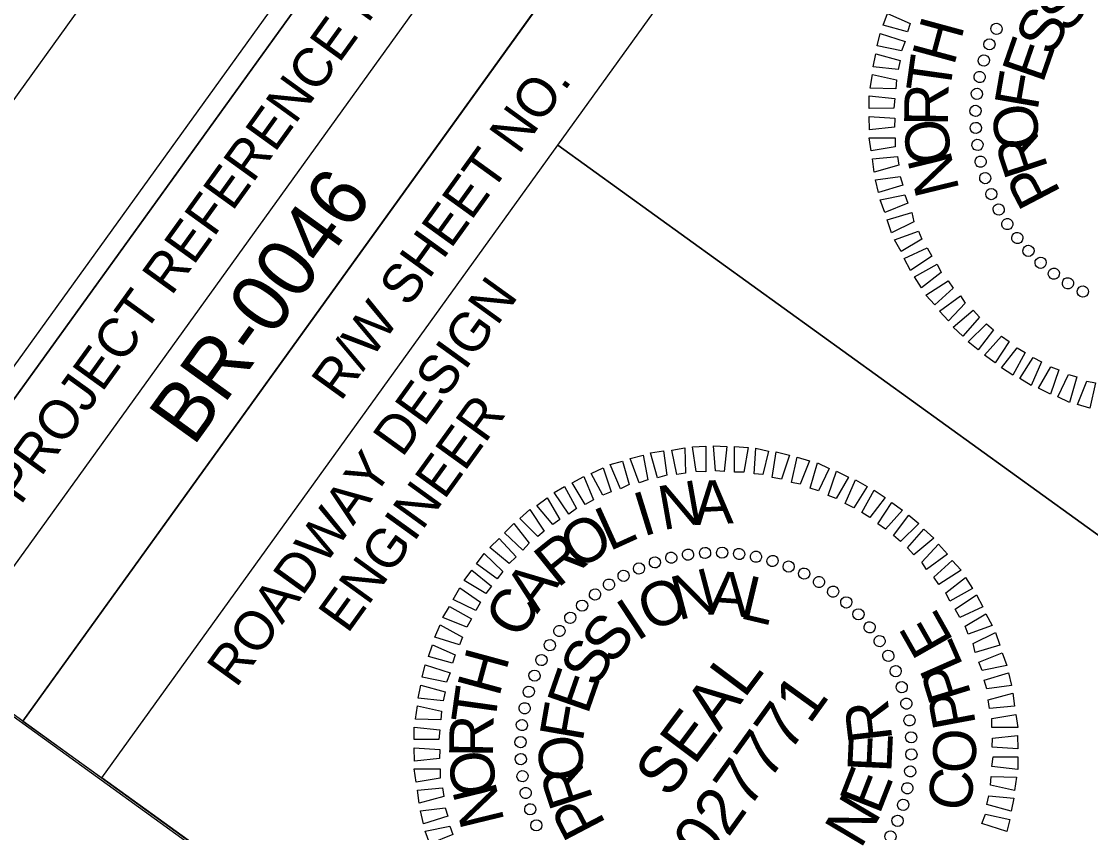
# Model space of a CAD drawing. Extents: x 2189185 to 2191058, y 386509 to 388561.
# Drawn here: x 2190081.4 to 2190218.6, y 388297.3 to 388401.3 of the extents above; entities that cross this region are included whole.
import ezdxf

# ---------------------------------------------------------------- set-up
doc = ezdxf.new("R2010")
doc.units = 0
for name, color, linetype in [('Sheet Clip Boundary CELL', 7, 'Continuous'), ('Sheet Cutting Line CELL', 7, 'Continuous'), ('Sheet Data Field CELL', 7, 'Continuous'), ('Sheet Plan CELL', 7, 'Continuous'), ('Sheet Plan Layout CELL', 7, 'Continuous'), ('Sheet Plot Border Inside CELL', 7, 'Continuous'), ('Sheet Plot Border Outside CELL', 7, 'Continuous'), ('Sheet Professional Seal CELL', 7, 'Continuous'), ('Sheet Sticker Exception Certification CELL', 7, 'Continuous')]:
    doc.layers.add(name, color=color, linetype=linetype)

msp = doc.modelspace()

# ---------------------------------------------------------------- linework, layer by layer
at = {"layer": 'Sheet Clip Boundary CELL'}
msp.add_lwpolyline([(2190166.8, 386710.01), (2190905.33, 387738.93), (2190256.9, 388232.77), (2190233.39, 388201.76), (2190061.07, 388326.03), (2189853.58, 388001.31), (2189912.61, 387915.43), (2189757.61, 387710.51), (2189654.64, 387750.49), (2189330.08, 387312.42)], close=True, dxfattribs=at)
at = {"layer": 'Sheet Cutting Line CELL'}
msp.add_line((2190169.94, 388515.44), (2189185.21, 387149.98), dxfattribs=at)
at = {"layer": 'Sheet Plan CELL'}
for p, q in [((2190071.39, 388318.9), (2190188.41, 388481.15)), ((2190081.56, 388311.57), (2190198.55, 388473.83)), ((2190081.56, 388311.57), (2190198.55, 388473.83)), ((2190150.21, 388385.42), (2190241.44, 388319.64)), ((2190081.56, 388311.57), (2190091.69, 388304.27))]:
    msp.add_line(p, q, dxfattribs=at)
for points in [[(2190178.25, 388488.52), (2189300.83, 387271.86), (2190152.47, 386657.68), (2191029.88, 387874.32)], [(2190061.21, 388326.25), (2190178.25, 388488.52), (2190198.55, 388473.83), (2190081.56, 388311.57)], [(2190150.21, 388385.42), (2190208.69, 388466.52), (2190299.95, 388400.72), (2190241.47, 388319.6)], [(2190152.47, 386657.68), (2189300.84, 387271.83), (2190061.21, 388326.25), (2190182.93, 388238.48), (2190299.95, 388400.72), (2191029.88, 387874.32)], [(2190091.69, 388304.27), (2190150.21, 388385.42), (2190241.47, 388319.6), (2190182.93, 388238.48)]]:
    msp.add_lwpolyline(points, close=True, dxfattribs=at)
at = {"layer": 'Sheet Plan Layout CELL'}
msp.add_lwpolyline([(2190209.82, 388170.73), (2190349.78, 388364.8), (2190178.26, 388488.53), (2190038.29, 388294.44)], close=True, dxfattribs=at)
at = {"layer": 'Sheet Plot Border Inside CELL'}
msp.add_lwpolyline([(2190064.73, 386531.72), (2191039.21, 387882.98), (2190183.53, 388500.09), (2189209.04, 387148.83)], close=True, dxfattribs=at)
at = {"layer": 'Sheet Plot Border Outside CELL'}
msp.add_lwpolyline([(2190073.35, 386509.48), (2191058.08, 387874.94), (2190169.94, 388515.44), (2189185.21, 387149.98)], close=True, dxfattribs=at)
at = {"layer": 'Sheet Professional Seal CELL'}
for p, q in [((2190206.5, 388400.33), (2190206.5, 388400.33)), ((2190205.54, 388398.31), (2190205.54, 388398.31)), ((2190204.8, 388396.26), (2190204.8, 388396.26)), ((2190204.28, 388394.17), (2190204.28, 388394.17)), ((2190203.95, 388392), (2190203.95, 388392)), ((2190203.77, 388389.79), (2190203.77, 388389.79)), ((2190203.76, 388387.63), (2190203.76, 388387.63)), ((2190204.01, 388385.42), (2190204.01, 388385.42)), ((2190204.39, 388383.3), (2190204.39, 388383.3)), ((2190205.02, 388381.18), (2190205.02, 388381.18)), ((2190205.75, 388379.11), (2190205.75, 388379.11)), ((2190206.75, 388377.16), (2190206.75, 388377.16)), ((2190207.84, 388375.26), (2190207.84, 388375.26)), ((2190209.14, 388373.46), (2190209.14, 388373.46)), ((2190210.58, 388371.87), (2190210.58, 388371.87)), ((2190212.12, 388370.33), (2190212.12, 388370.33)), ((2190213.81, 388368.92), (2190213.81, 388368.92)), ((2190215.63, 388367.67), (2190215.63, 388367.67)), ((2190217.55, 388366.66), (2190217.55, 388366.66)), ((2190169.11, 388333.18), (2190169.11, 388333.18)), ((2190171.26, 388333.17), (2190171.26, 388333.17)), ((2190162.66, 388331.92), (2190162.66, 388331.92)), ((2190164.77, 388332.55), (2190164.77, 388332.55)), ((2190166.9, 388332.93), (2190166.9, 388332.93)), ((2190173.48, 388332.99), (2190173.48, 388332.99)), ((2190175.64, 388332.66), (2190175.64, 388332.66)), ((2190177.73, 388332.14), (2190177.73, 388332.14)), ((2190160.59, 388331.19), (2190160.59, 388331.19)), ((2190179.79, 388331.4), (2190179.79, 388331.4)), ((2190181.81, 388330.44), (2190181.81, 388330.44)), ((2190156.74, 388329.1), (2190156.74, 388329.1)), ((2190158.64, 388330.19), (2190158.64, 388330.19)), ((2190183.73, 388329.42), (2190183.73, 388329.42)), ((2190154.94, 388327.8), (2190154.94, 388327.8)), ((2190185.54, 388328.18), (2190185.54, 388328.18)), ((2190153.35, 388326.36), (2190153.35, 388326.36)), ((2190187.24, 388326.77), (2190187.24, 388326.77)), ((2190188.77, 388325.23), (2190188.77, 388325.23)), ((2190151.81, 388324.82), (2190151.81, 388324.82)), ((2190190.21, 388323.63), (2190190.21, 388323.63)), ((2190150.4, 388323.13), (2190150.4, 388323.13)), ((2190149.15, 388321.31), (2190149.15, 388321.31)), ((2190191.51, 388321.84), (2190191.51, 388321.84)), ((2190192.6, 388319.94), (2190192.6, 388319.94)), ((2190148.14, 388319.39), (2190148.14, 388319.39)), ((2190147.17, 388317.38), (2190147.17, 388317.38)), ((2190193.6, 388317.98), (2190193.6, 388317.98)), ((2190194.33, 388315.92), (2190194.33, 388315.92)), ((2190146.43, 388315.32), (2190146.43, 388315.32)), ((2190145.91, 388313.23), (2190145.91, 388313.23)), ((2190194.96, 388313.8), (2190194.96, 388313.8)), ((2190195.34, 388311.68), (2190195.34, 388311.68)), ((2190145.58, 388311.06), (2190145.58, 388311.06)), ((2190145.4, 388308.85), (2190145.4, 388308.85)), ((2190195.59, 388309.46), (2190195.59, 388309.46)), ((2190170.49, 388308.08), (2190170.49, 388308.08)), ((2190195.58, 388307.31), (2190195.58, 388307.31)), ((2190145.39, 388306.7), (2190145.39, 388306.7)), ((2190145.65, 388304.48), (2190145.65, 388304.48)), ((2190195.4, 388305.1), (2190195.4, 388305.1)), ((2190146.03, 388302.36), (2190146.03, 388302.36)), ((2190195.07, 388302.93), (2190195.07, 388302.93)), ((2190194.55, 388300.84), (2190194.55, 388300.84)), ((2190146.65, 388300.24), (2190146.65, 388300.24)), ((2190147.38, 388298.18), (2190147.38, 388298.18)), ((2190193.81, 388298.78), (2190193.81, 388298.78))]:
    msp.add_line(p, q, dxfattribs=at)
for points in [[(2190195.07, 388399.94), (2190191.96, 388400.77), (2190192.51, 388402.29), (2190195.4, 388401)], [(2190194.29, 388397.49), (2190191.17, 388398.13), (2190191.56, 388399.7), (2190194.77, 388398.68)], [(2190193.85, 388395.09), (2190190.64, 388395.43), (2190190.98, 388397.1), (2190194.13, 388396.25)], [(2190193.57, 388392.64), (2190190.29, 388392.72), (2190190.55, 388394.45), (2190193.64, 388393.77)], [(2190193.29, 388390.13), (2190190.14, 388390.12), (2190190.13, 388391.73), (2190193.45, 388391.37)], [(2190193.4, 388387.71), (2190190.19, 388387.37), (2190190.13, 388389.08), (2190193.43, 388388.86)], [(2190193.49, 388385.18), (2190190.41, 388384.68), (2190190.14, 388386.36), (2190193.47, 388386.36)], [(2190193.94, 388382.82), (2190190.79, 388381.95), (2190190.58, 388383.64), (2190193.76, 388383.94)], [(2190194.46, 388380.29), (2190191.35, 388379.32), (2190190.94, 388380.97), (2190194.14, 388381.38)], [(2190195.12, 388377.96), (2190192.16, 388376.77), (2190191.54, 388378.38), (2190194.73, 388379.04)], [(2190195.87, 388375.57), (2190193.01, 388374.18), (2190192.46, 388375.81), (2190195.6, 388376.75)], [(2190196.91, 388373.34), (2190194.23, 388371.76), (2190193.41, 388373.28), (2190196.49, 388374.39)], [(2190198.19, 388371.19), (2190195.44, 388369.35), (2190194.62, 388370.86), (2190197.59, 388372.24)], [(2190199.39, 388369.09), (2190196.84, 388367.1), (2190195.97, 388368.54), (2190198.86, 388370.15)], [(2190200.9, 388367.08), (2190198.56, 388364.94), (2190197.42, 388366.19), (2190200.28, 388368.02)], [(2190202.46, 388365.15), (2190200.32, 388362.87), (2190199.15, 388364.14), (2190201.84, 388366.09)], [(2190204.3, 388363.33), (2190202.18, 388360.91), (2190200.92, 388362.07), (2190203.47, 388364.24)], [(2190206.1, 388361.72), (2190204.11, 388359.15), (2190202.83, 388360.19), (2190205.18, 388362.51)], [(2190208.1, 388360.22), (2190206.32, 388357.5), (2190204.94, 388358.49), (2190207.12, 388360.92)], [(2190210.15, 388358.8), (2190208.58, 388355.93), (2190207.14, 388356.84), (2190209.12, 388359.42)], [(2190212.27, 388357.64), (2190210.94, 388354.59), (2190209.47, 388355.47), (2190211.18, 388358.18)], [(2190214.48, 388356.6), (2190213.41, 388353.49), (2190211.86, 388354.24), (2190213.46, 388356.97)], [(2190216.78, 388355.68), (2190215.84, 388352.41), (2190214.33, 388353.14), (2190215.73, 388356.01)], [(2190219.2, 388354.93), (2190218.47, 388351.69), (2190216.89, 388352.15), (2190218.05, 388355.14)], [(2190160.64, 388342.12), (2190159.5, 388345.23), (2190161.15, 388345.64), (2190161.77, 388342.48)], [(2190163.01, 388342.76), (2190162.1, 388345.94), (2190163.78, 388346.21), (2190164.18, 388343.09)], [(2190165.48, 388343.19), (2190164.84, 388346.31), (2190166.51, 388346.58), (2190166.57, 388343.33)], [(2190167.97, 388343.56), (2190167.49, 388346.74), (2190169.2, 388346.8), (2190169.19, 388343.54)], [(2190170.43, 388343.64), (2190170.16, 388346.85), (2190171.89, 388346.77), (2190171.55, 388343.57)], [(2190172.85, 388343.49), (2190172.86, 388346.75), (2190174.63, 388346.64), (2190174.07, 388343.47)], [(2190175.4, 388343.26), (2190175.61, 388346.55), (2190177.25, 388346.17), (2190176.52, 388343.19)], [(2190177.72, 388342.81), (2190178.23, 388346.08), (2190179.91, 388345.67), (2190178.91, 388342.57)], [(2190158.23, 388341.34), (2190156.9, 388344.45), (2190158.51, 388344.89), (2190159.36, 388341.88)], [(2190180.16, 388342.17), (2190180.89, 388345.4), (2190182.47, 388344.94), (2190181.3, 388341.96)], [(2190182.57, 388341.41), (2190183.51, 388344.68), (2190185.02, 388343.96), (2190183.63, 388341.08)], [(2190153.71, 388339.35), (2190152.05, 388342.09), (2190153.53, 388342.94), (2190154.8, 388339.92)], [(2190155.99, 388340.54), (2190154.47, 388343.31), (2190156.04, 388344.03), (2190157.04, 388340.96)], [(2190184.87, 388340.49), (2190185.94, 388343.61), (2190187.49, 388342.85), (2190185.9, 388340.12)], [(2190151.63, 388338.08), (2190149.75, 388340.86), (2190151.05, 388341.64), (2190152.58, 388338.81)], [(2190187.08, 388339.46), (2190188.41, 388342.5), (2190189.88, 388341.63), (2190188.17, 388338.92)], [(2190149.58, 388336.78), (2190147.51, 388339.21), (2190148.82, 388340.17), (2190150.48, 388337.43)], [(2190189.2, 388338.3), (2190190.78, 388341.17), (2190192.21, 388340.25), (2190190.23, 388337.67)], [(2190147.65, 388335.22), (2190145.31, 388337.52), (2190146.63, 388338.67), (2190148.47, 388335.92)], [(2190191.26, 388336.87), (2190193.04, 388339.6), (2190194.42, 388338.6), (2190192.23, 388336.17)], [(2190193.26, 388335.37), (2190195.24, 388337.95), (2190196.52, 388336.9), (2190194.17, 388334.59)], [(2190145.71, 388333.47), (2190143.38, 388335.71), (2190144.55, 388336.9), (2190146.54, 388334.36)], [(2190195.06, 388333.76), (2190197.17, 388336.18), (2190198.43, 388335.03), (2190195.88, 388332.86)], [(2190143.98, 388331.76), (2190141.47, 388333.82), (2190142.67, 388334.98), (2190144.85, 388332.61)], [(2190196.89, 388331.95), (2190199.03, 388334.23), (2190200.2, 388332.95), (2190197.51, 388331.01)], [(2190142.4, 388329.82), (2190139.76, 388331.72), (2190140.77, 388333.03), (2190143.14, 388330.76)], [(2190198.46, 388330.02), (2190200.8, 388332.15), (2190201.93, 388330.9), (2190199.07, 388329.08)], [(2190140.96, 388327.9), (2190138.17, 388329.6), (2190139.18, 388330.91), (2190141.7, 388328.85)], [(2190199.96, 388328), (2190202.51, 388329.99), (2190203.39, 388328.56), (2190200.49, 388326.94)], [(2190139.7, 388325.73), (2190136.78, 388327.15), (2190137.61, 388328.65), (2190140.28, 388326.79)], [(2190201.16, 388325.91), (2190203.91, 388327.75), (2190204.73, 388326.23), (2190201.76, 388324.86)], [(2190138.54, 388323.61), (2190135.47, 388324.83), (2190136.32, 388326.25), (2190139.12, 388324.67)], [(2190202.44, 388323.75), (2190205.13, 388325.33), (2190205.94, 388323.82), (2190202.86, 388322.71)], [(2190137.58, 388321.34), (2190134.41, 388322.33), (2190135.12, 388323.91), (2190137.99, 388322.33)], [(2190203.49, 388321.52), (2190206.34, 388322.91), (2190206.89, 388321.28), (2190203.75, 388320.34)], [(2190136.7, 388319.01), (2190133.6, 388319.83), (2190134.14, 388321.35), (2190137.03, 388320.07)], [(2190204.23, 388319.13), (2190207.19, 388320.33), (2190207.81, 388318.71), (2190204.62, 388318.05)], [(2190135.92, 388316.55), (2190132.81, 388317.2), (2190133.2, 388318.76), (2190136.41, 388317.74)], [(2190204.9, 388316.81), (2190208, 388317.77), (2190208.41, 388316.12), (2190205.22, 388315.71)], [(2190135.48, 388314.16), (2190132.28, 388314.5), (2190132.61, 388316.16), (2190135.76, 388315.31)], [(2190205.41, 388314.27), (2190208.57, 388315.14), (2190208.77, 388313.46), (2190205.59, 388313.16)], [(2190135.2, 388311.71), (2190131.93, 388311.79), (2190132.18, 388313.51), (2190135.27, 388312.83)], [(2190205.87, 388311.91), (2190208.94, 388312.41), (2190209.21, 388310.73), (2190205.88, 388310.73)], [(2190134.93, 388309.19), (2190131.77, 388309.19), (2190131.76, 388310.8), (2190135.08, 388310.44)], [(2190205.95, 388309.38), (2190209.16, 388309.72), (2190209.22, 388308.01), (2190205.93, 388308.23)], [(2190135.03, 388306.78), (2190131.83, 388306.44), (2190131.76, 388308.15), (2190135.06, 388307.93)], [(2190206.06, 388306.97), (2190209.21, 388306.97), (2190209.22, 388305.36), (2190205.9, 388305.72)], [(2190135.12, 388304.25), (2190132.05, 388303.75), (2190131.78, 388305.43), (2190135.11, 388305.43)], [(2190205.79, 388304.45), (2190209.06, 388304.37), (2190208.8, 388302.65), (2190205.72, 388303.33)], [(2190135.57, 388301.89), (2190132.42, 388301.02), (2190132.22, 388302.7), (2190135.39, 388303)], [(2190205.5, 388302), (2190208.71, 388301.66), (2190208.37, 388300), (2190205.22, 388300.85)], [(2190136.09, 388299.36), (2190132.99, 388298.39), (2190132.58, 388300.04), (2190135.77, 388300.45)], [(2190205.07, 388299.61), (2190208.18, 388298.96), (2190207.79, 388297.4), (2190204.58, 388298.42)], [(2190136.75, 388297.03), (2190133.8, 388295.83), (2190133.17, 388297.45), (2190136.36, 388298.11)]]:
    msp.add_lwpolyline(points, close=True, dxfattribs=at)
for centre, major_axis in [((2190206.47, 388400.32), (-0.643, 0.325)), ((2190205.57, 388398.33), (-0.669, 0.267)), ((2190204.85, 388396.26), (-0.689, 0.208)), ((2190204.31, 388394.14), (-0.705, 0.147)), ((2190203.96, 388391.98), (-0.715, 0.085)), ((2190203.79, 388389.8), (-0.72, 0.023)), ((2190203.82, 388387.61), (-0.719, -0.04)), ((2190204.04, 388385.44), (-0.713, -0.103)), ((2190204.44, 388383.29), (-0.701, -0.164)), ((2190205.04, 388381.18), (-0.684, -0.225)), ((2190205.81, 388379.13), (-0.662, -0.284)), ((2190206.76, 388377.16), (-0.635, -0.34)), ((2190207.87, 388375.28), (-0.602, -0.394)), ((2190209.15, 388373.5), (-0.566, -0.445)), ((2190210.58, 388371.85), (-0.525, -0.493)), ((2190212.14, 388370.32), (-0.48, -0.537)), ((2190213.84, 388368.93), (-0.431, -0.577)), ((2190215.64, 388367.7), (-0.379, -0.612)), ((2190217.55, 388366.63), (-0.325, -0.643)), ((2190164.76, 388332.5), (-0.164, 0.701)), ((2190166.91, 388332.9), (-0.103, 0.713)), ((2190169.09, 388333.12), (-0.04, 0.719)), ((2190171.28, 388333.15), (0.023, 0.72)), ((2190173.46, 388332.98), (0.085, 0.715)), ((2190175.62, 388332.63), (0.147, 0.705)), ((2190160.61, 388331.13), (-0.284, 0.662)), ((2190162.66, 388331.91), (-0.225, 0.684)), ((2190177.74, 388332.09), (0.208, 0.689)), ((2190179.81, 388331.37), (0.267, 0.669)), ((2190158.64, 388330.18), (-0.34, 0.635)), ((2190181.8, 388330.47), (0.325, 0.643)), ((2190156.76, 388329.07), (-0.394, 0.602)), ((2190183.71, 388329.4), (0.379, 0.612)), ((2190154.98, 388327.79), (-0.445, 0.566)), ((2190185.52, 388328.16), (0.431, 0.577)), ((2190153.32, 388326.36), (-0.493, 0.525)), ((2190187.21, 388326.78), (0.48, 0.537)), ((2190151.8, 388324.8), (-0.537, 0.48)), ((2190188.77, 388325.25), (0.525, 0.493)), ((2190150.41, 388323.1), (-0.577, 0.431)), ((2190190.2, 388323.59), (0.566, 0.445)), ((2190191.48, 388321.81), (0.602, 0.394)), ((2190149.18, 388321.3), (-0.612, 0.379)), ((2190148.11, 388319.39), (-0.643, 0.325)), ((2190192.6, 388319.93), (0.635, 0.34)), ((2190147.21, 388317.39), (-0.669, 0.267)), ((2190193.54, 388317.96), (0.662, 0.284)), ((2190194.32, 388315.91), (0.684, 0.225)), ((2190146.48, 388315.33), (-0.689, 0.208)), ((2190145.94, 388313.21), (-0.705, 0.147)), ((2190194.91, 388313.81), (0.701, 0.164)), ((2190145.59, 388311.05), (-0.715, 0.085)), ((2190195.32, 388311.66), (0.713, 0.103)), ((2190195.53, 388309.48), (0.719, 0.04)), ((2190145.42, 388308.87), (-0.72, 0.023)), ((2190145.45, 388306.68), (-0.719, -0.04)), ((2190195.56, 388307.29), (0.72, -0.023)), ((2190195.4, 388305.11), (0.715, -0.085)), ((2190145.67, 388304.5), (-0.713, -0.103)), ((2190146.08, 388302.35), (-0.701, -0.164)), ((2190195.04, 388302.95), (0.705, -0.147)), ((2190194.5, 388300.83), (0.689, -0.208)), ((2190146.67, 388300.25), (-0.684, -0.225)), ((2190147.44, 388298.2), (-0.662, -0.284)), ((2190193.78, 388298.77), (0.669, -0.267)), ((2190192.88, 388296.77), (0.643, -0.325))]:
    msp.add_ellipse(centre, major_axis=major_axis, ratio=0.999708, dxfattribs=at)

# ---------------------------------------------------------------- texts
at = {"layer": 'Sheet Data Field CELL'}
msp.add_text('BR-0046', height=7.5, rotation=54.2018, dxfattribs=at).set_placement((2190103.44, 388346.64))
at = {"layer": 'Sheet Plan CELL'}
for s, height, p in [('PROJECT REFERENCE NO.', 5.0001, (2190081.28, 388339.15)), ('R/W SHEET NO.', 5.0001, (2190122.35, 388352.43)), ('ROADWAY DESIGN', 5.0001, (2190108.94, 388315.71)), ('ENGINEER', 5, (2190123.24, 388322.65))]:
    msp.add_text(s, height=height, rotation=54.2018, dxfattribs=at).set_placement(p)
at = {"layer": 'Sheet Professional Seal CELL'}
for s, height, rotation, p in [('S', 5.64, 52.1022, (2190215.62, 388399.55)), ('S', 5.64, 61.4575, (2190213.56, 388396.6)), ('H', 5.64, 74.8213, (2190201.02, 388395.46)), ('E', 5.64, 70.8129, (2190212.39, 388393.19)), ('T', 5.64, 82.0216, (2190200.46, 388391.86)), ('F', 5.64, 80.1689, (2190211.73, 388389.71)), ('R', 5.64, 89.2223, (2190200.26, 388387.82)), ('O', 5.64, 98.8831, (2190212.2, 388385.31)), ('O', 5.64, 96.4236, (2190200.75, 388383.21)), ('R', 5.64, 108.2415, (2190213.16, 388382.46)), ('N', 5.64, 103.6253, (2190201.76, 388379.65)), ('P', 5.64, 117.6007, (2190214.82, 388379.29)), ('N', 5.64, 10.0208, (2190163.64, 388336.02)), ('A', 5.64, 2.819, (2190167.76, 388336.68)), ('I', 5.64, 17.222, (2190161.12, 388335.18)), ('L', 5.64, 24.4227, (2190156.81, 388333.3)), ('O', 5.64, 31.623, (2190152.73, 388330.81)), ('R', 5.64, 38.8229, (2190150.17, 388328.53)), ('A', 5.64, 53.2222, (2190147.55, 388325.24)), ('N', 5.64, 14.6785, (2190165.66, 388324.45)), ('A', 5.64, 355.9621, (2190169.43, 388325.24)), ('O', 5.64, 24.0353, (2190162.07, 388322.91)), ('L', 5.64, 346.6027, (2190173.37, 388324.81)), ('C', 5.64, 60.4217, (2190145.48, 388321.86)), ('I', 5.64, 33.3914, (2190160.34, 388321.69)), ('S', 5.64, 52.1022, (2190157.25, 388318.61)), ('E', 5.5, 119.5477, (2190201.05, 388321.83)), ('S', 5.64, 61.4575, (2190155.19, 388315.67)), ('L', 5.5, 113.7375, (2190202.28, 388318.67)), ('H', 5.64, 74.8213, (2190142.66, 388314.53)), ('E', 5.64, 70.8129, (2190154.02, 388312.25)), ('SEAL', 5.998, 53.2018, (2190164.5, 388301.49)), ('P', 5.5, 107.1545, (2190203.29, 388314.95)), ('027771', 5.998, 54.2018, (2190169.44, 388292.93)), ('T', 5.64, 82.0216, (2190142.09, 388310.93)), ('F', 5.64, 80.1689, (2190153.37, 388308.78)), ('R', 5.64, 96.6833, (2190193.14, 388309.13)), ('P', 5.5, 100.5715, (2190203.86, 388311.15)), ('R', 5.64, 89.2223, (2190141.89, 388306.88)), ('O', 5.5, 89.867, (2190203.85, 388304.89)), ('O', 5.64, 98.8831, (2190153.83, 388304.38)), ('E', 5.64, 87.3259, (2190192.97, 388304.88)), ('O', 5.64, 96.4236, (2190142.39, 388302.27)), ('R', 5.64, 108.2415, (2190154.79, 388301.53)), ('E', 5.64, 68.6136, (2190191.45, 388299.44)), ('C', 5.5, 80.9943, (2190202.96, 388299.79)), ('N', 5.64, 103.6253, (2190143.39, 388298.71)), ('N', 5.64, 59.2582, (2190189.04, 388295.07)), ('P', 5.64, 117.6007, (2190156.45, 388298.36))]:
    msp.add_text(s, height=height, rotation=rotation, dxfattribs=at).set_placement(p)
at = {"layer": 'Sheet Sticker Exception Certification CELL'}
for s, p in [('DOCUMENT NOT CONSIDERED FINAL', (2190203.65, 388249.52)), ('DOCUMENT NOT CONSIDERED FINAL', (2190203.65, 388249.52)), ('UNLESS ALL SIGNATURES COMPLETED', (2190207.82, 388240.26)), ('UNLESS ALL SIGNATURES COMPLETED', (2190207.82, 388240.26))]:
    msp.add_text(s, height=5.5, rotation=54.2018, dxfattribs=at).set_placement(p)

doc.saveas('drawing.dxf')
